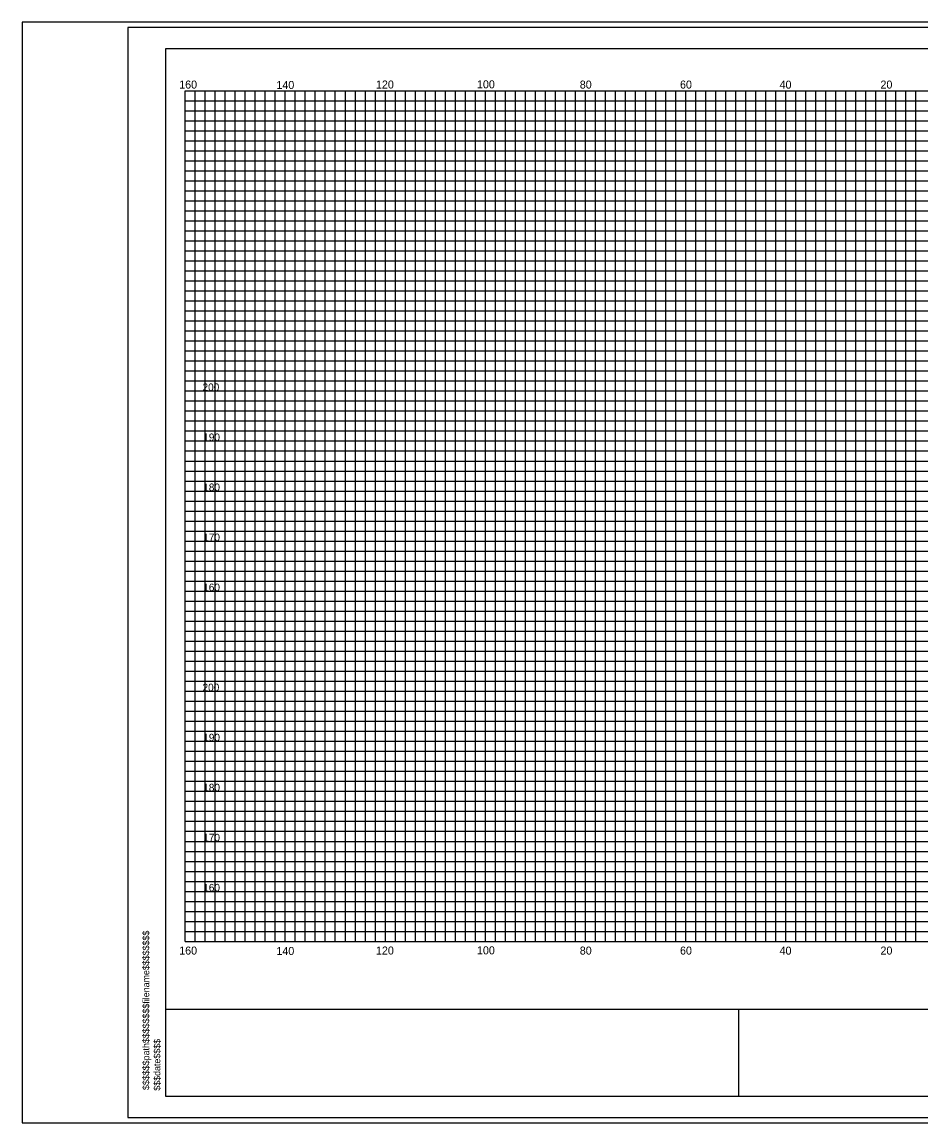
# Model space of a CAD drawing. Extents: x 967 to 1326, y 964 to 1184.
# Drawn here: x 967.4 to 1147, y 963.7 to 1183.7 of the extents above; entities that cross this region are included whole.
import ezdxf

# ---------------------------------------------------------------- set-up
doc = ezdxf.new("R2010")
doc.units = 0
for name, color, linetype in [('Default', 7, 'Continuous'), ('RD_SHT_Bndy', 7, 'Continuous'), ('RD_SHT_IplotShp', 7, 'Continuous'), ('RD_SHT_MjGrid', 7, 'Continuous'), ('RD_SHT_MnGrid', 7, 'Continuous'), ('RD_SHT_TX', 7, 'Continuous'), ('RD_Sketch1', 7, 'Continuous')]:
    doc.layers.add(name, color=color, linetype=linetype)

msp = doc.modelspace()

# ---------------------------------------------------------------- linework, layer by layer
at = {"layer": 'RD_SHT_Bndy'}
for p, q in [((996.11, 968.98), (996.11, 1178.46)), ((996.11, 1178.46), (1323.89, 1178.46)), ((996.11, 986.49), (1323.89, 986.49)), ((1110.59, 968.98), (1110.59, 986.56)), ((1323.89, 968.98), (996.11, 968.98))]:
    msp.add_line(p, q, dxfattribs=at)
at = {"layer": 'RD_SHT_IplotShp'}
for points in [[(967.41, 963.72), (1326.28, 963.72), (1326.28, 1183.72), (967.41, 1183.72)], [(988.52, 964.84), (1326.28, 964.84), (1326.28, 1182.6), (988.52, 1182.6)]]:
    msp.add_lwpolyline(points, close=True, dxfattribs=at)
at = {"layer": 'RD_SHT_MjGrid'}
for p, q in [((1000, 1170), (1320, 1170)), ((1000, 1000), (1000, 1170)), ((1010, 1000), (1010, 1170)), ((1020, 1000), (1020, 1170)), ((1030, 1000), (1030, 1170)), ((1040, 1000), (1040, 1170)), ((1050, 1000), (1050, 1170)), ((1060, 1000), (1060, 1170)), ((1070, 1000), (1070, 1170)), ((1080, 1000), (1080, 1170)), ((1090, 1000), (1090, 1170)), ((1100, 1000), (1100, 1170)), ((1110, 1000), (1110, 1170)), ((1120, 1000), (1120, 1170)), ((1130, 1000), (1130, 1170)), ((1140, 1000), (1140, 1170)), ((1000, 1160), (1320, 1160)), ((1000, 1150), (1320, 1150)), ((1000, 1140), (1320, 1140)), ((1000, 1130), (1320, 1130)), ((1000, 1120), (1320, 1120)), ((1000, 1110), (1320, 1110)), ((1000, 1100), (1320, 1100)), ((1000, 1090), (1320, 1090)), ((1000, 1080), (1320, 1080)), ((1000, 1070), (1320, 1070)), ((1000, 1060), (1320, 1060)), ((1000, 1050), (1320, 1050)), ((1000, 1040), (1320, 1040)), ((1000, 1030), (1320, 1030)), ((1000, 1020), (1320, 1020)), ((1000, 1010), (1320, 1010)), ((1000, 1000), (1320, 1000))]:
    msp.add_line(p, q, dxfattribs=at)
at = {"layer": 'RD_SHT_MnGrid'}
for p, q in [((1002, 1000), (1002, 1170)), ((1004, 1000), (1004, 1170)), ((1006, 1000), (1006, 1170)), ((1008, 1000), (1008, 1170)), ((1012, 1000), (1012, 1170)), ((1014, 1000), (1014, 1170)), ((1016, 1000), (1016, 1170)), ((1018, 1000), (1018, 1170)), ((1022, 1000), (1022, 1170)), ((1024, 1000), (1024, 1170)), ((1026, 1000), (1026, 1170)), ((1028, 1000), (1028, 1170)), ((1032, 1000), (1032, 1170)), ((1034, 1000), (1034, 1170)), ((1036, 1000), (1036, 1170)), ((1038, 1000), (1038, 1170)), ((1042, 1000), (1042, 1170)), ((1044, 1000), (1044, 1170)), ((1046, 1000), (1046, 1170)), ((1048, 1000), (1048, 1170)), ((1052, 1000), (1052, 1170)), ((1054, 1000), (1054, 1170)), ((1056, 1000), (1056, 1170)), ((1058, 1000), (1058, 1170)), ((1062, 1000), (1062, 1170)), ((1064, 1000), (1064, 1170)), ((1066, 1000), (1066, 1170)), ((1068, 1000), (1068, 1170)), ((1072, 1000), (1072, 1170)), ((1074, 1000), (1074, 1170)), ((1076, 1000), (1076, 1170)), ((1078, 1000), (1078, 1170)), ((1082, 1000), (1082, 1170)), ((1084, 1000), (1084, 1170)), ((1086, 1000), (1086, 1170)), ((1088, 1000), (1088, 1170)), ((1092, 1000), (1092, 1170)), ((1094, 1000), (1094, 1170)), ((1096, 1000), (1096, 1170)), ((1098, 1000), (1098, 1170)), ((1102, 1000), (1102, 1170)), ((1104, 1000), (1104, 1170)), ((1106, 1000), (1106, 1170)), ((1108, 1000), (1108, 1170)), ((1112, 1000), (1112, 1170)), ((1114, 1000), (1114, 1170)), ((1116, 1000), (1116, 1170)), ((1118, 1000), (1118, 1170)), ((1122, 1000), (1122, 1170)), ((1124, 1000), (1124, 1170)), ((1126, 1000), (1126, 1170)), ((1128, 1000), (1128, 1170)), ((1132, 1000), (1132, 1170)), ((1134, 1000), (1134, 1170)), ((1136, 1000), (1136, 1170)), ((1138, 1000), (1138, 1170)), ((1142, 1000), (1142, 1170)), ((1144, 1000), (1144, 1170)), ((1146, 1000), (1146, 1170)), ((1000, 1168), (1320, 1168)), ((1000, 1166), (1320, 1166)), ((1000, 1164), (1320, 1164)), ((1000, 1162), (1320, 1162)), ((1000, 1158), (1320, 1158)), ((1000, 1156), (1320, 1156)), ((1000, 1154), (1320, 1154)), ((1000, 1152), (1320, 1152)), ((1000, 1148), (1320, 1148)), ((1000, 1146), (1320, 1146)), ((1000, 1144), (1320, 1144)), ((1000, 1142), (1320, 1142)), ((1000, 1138), (1320, 1138)), ((1000, 1136), (1320, 1136)), ((1000, 1134), (1320, 1134)), ((1000, 1132), (1320, 1132)), ((1000, 1128), (1320, 1128)), ((1000, 1126), (1320, 1126)), ((1000, 1124), (1320, 1124)), ((1000, 1122), (1320, 1122)), ((1000, 1118), (1320, 1118)), ((1000, 1116), (1320, 1116)), ((1000, 1114), (1320, 1114)), ((1000, 1112), (1320, 1112)), ((1000, 1108), (1320, 1108)), ((1000, 1106), (1320, 1106)), ((1000, 1104), (1320, 1104)), ((1000, 1102), (1320, 1102)), ((1000, 1098), (1320, 1098)), ((1000, 1096), (1320, 1096)), ((1000, 1094), (1320, 1094)), ((1000, 1092), (1320, 1092)), ((1000, 1088), (1320, 1088)), ((1000, 1086), (1320, 1086)), ((1000, 1084), (1320, 1084)), ((1000, 1082), (1320, 1082)), ((1000, 1078), (1320, 1078)), ((1000, 1076), (1320, 1076)), ((1000, 1074), (1320, 1074)), ((1000, 1072), (1320, 1072)), ((1000, 1068), (1320, 1068)), ((1000, 1066), (1320, 1066)), ((1000, 1064), (1320, 1064)), ((1000, 1062), (1320, 1062)), ((1000, 1058), (1320, 1058)), ((1000, 1056), (1320, 1056)), ((1000, 1054), (1320, 1054)), ((1000, 1052), (1320, 1052)), ((1000, 1048), (1320, 1048)), ((1000, 1046), (1320, 1046)), ((1000, 1044), (1320, 1044)), ((1000, 1042), (1320, 1042)), ((1000, 1038), (1320, 1038)), ((1000, 1036), (1320, 1036)), ((1000, 1034), (1320, 1034)), ((1000, 1032), (1320, 1032)), ((1000, 1028), (1320, 1028)), ((1000, 1026), (1320, 1026)), ((1000, 1024), (1320, 1024)), ((1000, 1022), (1320, 1022)), ((1000, 1018), (1320, 1018)), ((1000, 1016), (1320, 1016)), ((1000, 1014), (1320, 1014)), ((1000, 1012), (1320, 1012)), ((1000, 1008), (1320, 1008)), ((1000, 1006), (1320, 1006)), ((1000, 1004), (1320, 1004)), ((1000, 1002), (1320, 1002))]:
    msp.add_line(p, q, dxfattribs=at)
at = {"layer": 'RD_Sketch1'}
msp.add_lwpolyline([(967.41, 963.72), (1326.28, 963.72), (1326.28, 1183.72), (967.41, 1183.72)], close=True, dxfattribs=at)

# ---------------------------------------------------------------- texts
at = {"layer": 'Default'}
for s, p in [('200', (1003.47, 1110)), ('190', (1003.61, 1100)), ('180', (1003.61, 1090)), ('170', (1003.61, 1080)), ('160', (1003.61, 1070)), ('200', (1003.47, 1050)), ('190', (1003.61, 1040)), ('180', (1003.61, 1030)), ('170', (1003.61, 1020)), ('160', (1003.61, 1010))]:
    msp.add_text(s, height=1.5, dxfattribs=at).set_placement(p)
for s, p in [('$$$$$$path$$$$$$$$filename$$$$$$$$', (992.83, 970.31)), ('$$$date$$$$', (995.04, 970.17))]:
    msp.add_text(s, height=1.3258, rotation=90, dxfattribs=at).set_placement(p)
at = {"layer": 'RD_SHT_TX'}
for s, p in [('160', (998.81, 1170.42)), ('140', (1018.23, 1170.34)), ('120', (1038.12, 1170.43)), ('100', (1058.3, 1170.47)), ('80', (1078.84, 1170.42)), ('60', (1098.86, 1170.42)), ('40', (1118.75, 1170.41)), ('20', (1138.91, 1170.42)), ('160', (998.81, 997.37)), ('140', (1018.23, 997.29)), ('120', (1038.12, 997.38)), ('100', (1058.3, 997.42)), ('80', (1078.84, 997.37)), ('60', (1098.86, 997.37)), ('40', (1118.75, 997.36)), ('20', (1138.91, 997.37))]:
    msp.add_text(s, height=1.6, dxfattribs=at).set_placement(p)

doc.saveas('drawing.dxf')
